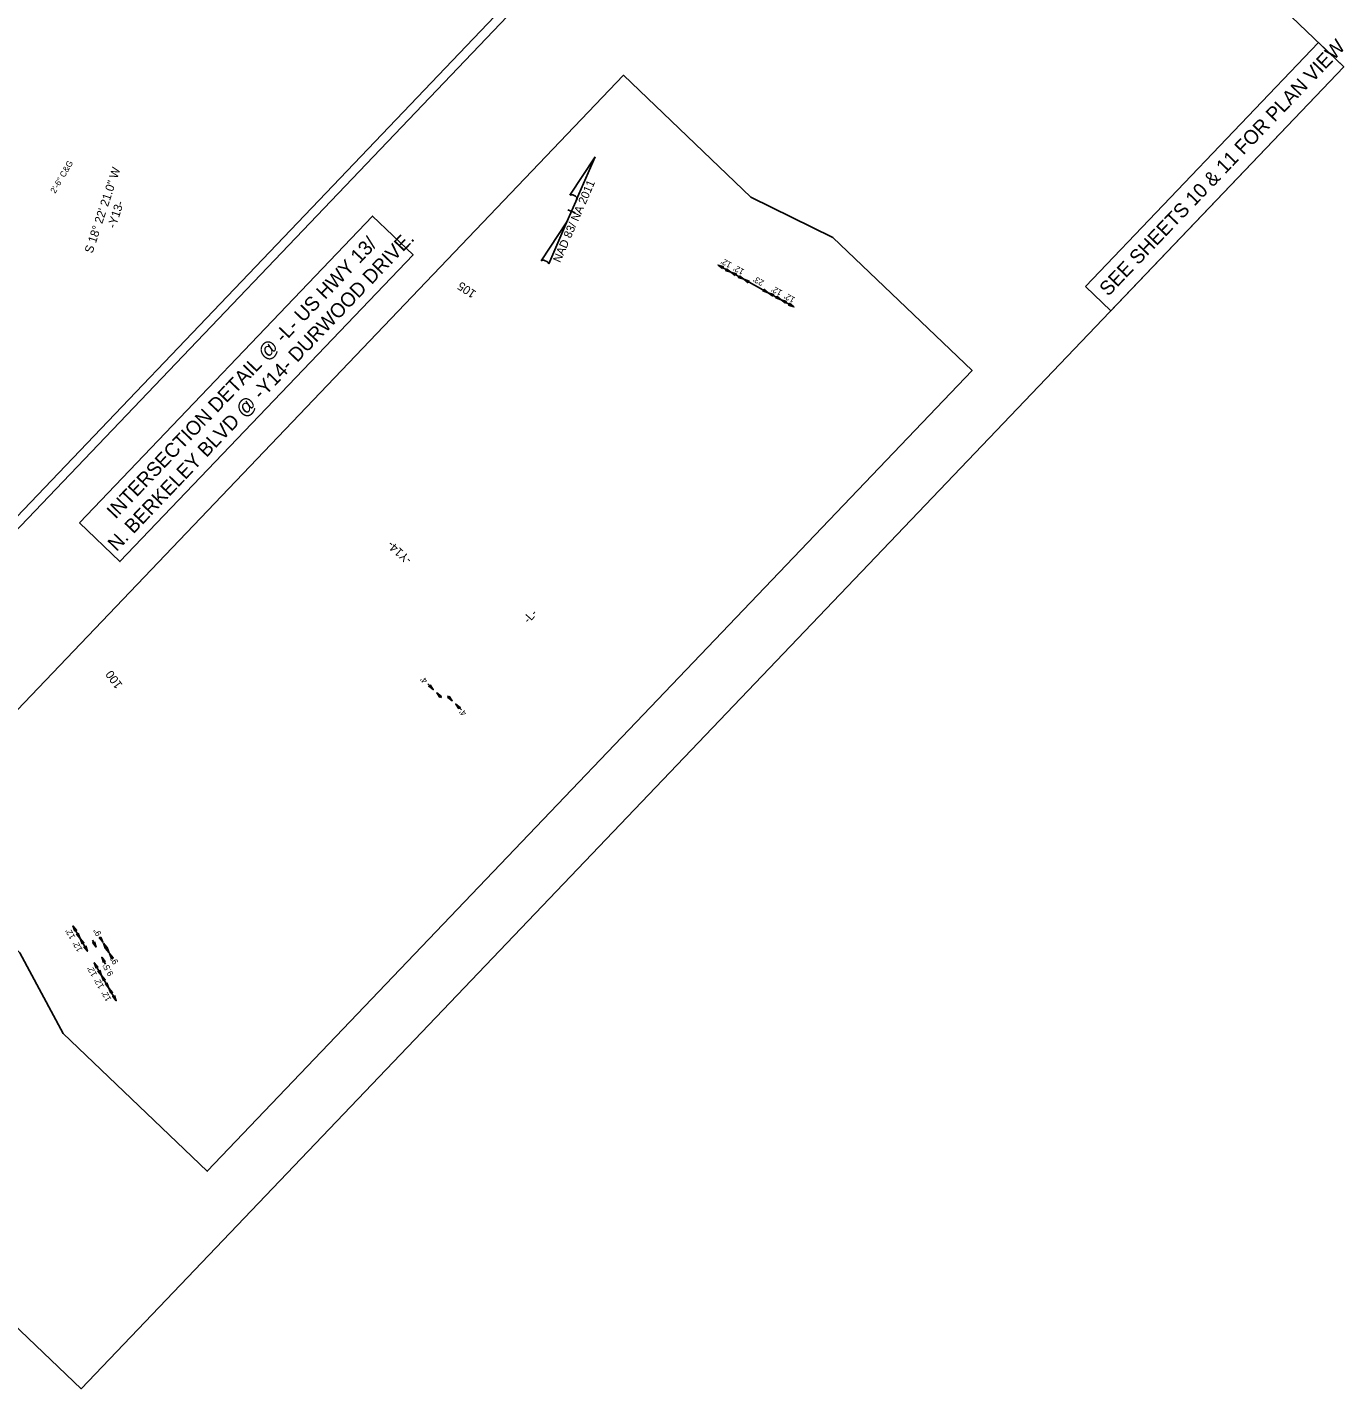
# Model space of a CAD drawing. Extents: x 2326836 to 2328631, y 602012 to 603789.
# Drawn here: x 2327551 to 2328631, y 602012 to 603129 of the extents above; entities that cross this region are included whole.
import ezdxf

# ---------------------------------------------------------------- set-up
doc = ezdxf.new("R2010")
doc.units = 0
for name, color, linetype in [('Default', 7, 'Continuous'), ('Prop Dimension', 7, 'Continuous'), ('Prop Dimension Text', 7, 'Continuous'), ('Prop Horizontal Alignment Direction Label', 7, 'Continuous'), ('Prop Horizontal Alignment Tick Label', 7, 'Continuous'), ('Prop North Arrow NAD83 for Plan Sheets CELL', 7, 'Continuous'), ('Prop Terminator CELL', 7, 'Continuous'), ('Scratch_Level_1', 7, 'Continuous'), ('Sheet Plan CELL', 7, 'Continuous')]:
    doc.layers.add(name, color=color, linetype=linetype)

msp = doc.modelspace()

# ---------------------------------------------------------------- linework, layer by layer
at = {"layer": 'Default'}
for points in [[(2328419.4, 602916.4), (2328610.7, 603116.6), (2328631.4, 603096.8), (2328440.1, 602896.6)], [(2327593.8, 602722.5), (2327834.4, 602974.3), (2327867.6, 602942.6), (2327627, 602690.8)]]:
    msp.add_lwpolyline(points, close=True, dxfattribs=at)
at = {"layer": 'Prop Dimension'}
for p, q in [((2328128.4, 602928.3), (2328117.9, 602934)), ((2328138.9, 602922.5), (2328128.4, 602928.3)), ((2328159.1, 602911.4), (2328138.9, 602922.5)), ((2328169.6, 602905.6), (2328159.1, 602911.4)), ((2328180.1, 602899.8), (2328169.6, 602905.6)), ((2327879.6, 602590.6), (2327884.2, 602585.9)), ((2327887, 602583.1), (2327890.8, 602579.1)), ((2327895.9, 602580.7), (2327899.8, 602576.7)), ((2327902.6, 602573.9), (2327907.3, 602569.2)), ((2327588.4, 602392), (2327594.4, 602381.6)), ((2327594.4, 602381.6), (2327600.4, 602371.2)), ((2327604.4, 602380.3), (2327607.5, 602374.6)), ((2327610.3, 602383), (2327613, 602378.5)), ((2327613.4, 602377.9), (2327616.1, 602373.4)), ((2327612.1, 602366.3), (2327615.2, 602360.5)), ((2327615.4, 602374.5), (2327618.1, 602370)), ((2327618.5, 602369.3), (2327621.2, 602364.8)), ((2327606, 602361.7), (2327612, 602351.3)), ((2327612, 602351.3), (2327618, 602340.9)), ((2327618, 602340.9), (2327624, 602330.6))]:
    msp.add_line(p, q, dxfattribs=at)
at = {"layer": 'Prop North Arrow NAD83 for Plan Sheets CELL'}
for p, q in [((2327996.2, 602991.5), (2328017, 603022.9)), ((2328017, 603022.8), (2328001.8, 602987.8)), ((2328017, 603022.8), (2328017, 603022.9)), ((2328017, 603022.8), (2328017, 603022.9)), ((2327993.9, 602969.6), (2328002.3, 602988.8)), ((2328001.8, 602987.8), (2328002.2, 602988.8)), ((2327993.9, 602969.6), (2327972.7, 602937.5)), ((2327979, 602935), (2327993.9, 602969.6)), ((2327994.7, 602979.3), (2327994.6, 602979.4)), ((2327994.7, 602979.3), (2328000.6, 602976.8)), ((2327997.3, 602978.2), (2327994.7, 602979.3))]:
    msp.add_line(p, q, dxfattribs=at)
for centre, start_param, end_param in [((2327999.1, 602989.8), 0.216388, 2.908219), ((2327975.8, 602936.1), 0.201328, 3.141593)]:
    msp.add_ellipse(centre, major_axis=(3.09, -1.37), ratio=0.461098, start_param=start_param, end_param=end_param, dxfattribs=at)
at = {"layer": 'Prop Terminator CELL'}
for points in [[(2328121.5, 602931.2), (2328117.9, 602934), (2328122.3, 602932.6), (2328121.4, 602932.1)], [(2328124.9, 602931.1), (2328128.4, 602928.3), (2328124.1, 602929.7), (2328125, 602930.2)], [(2328132, 602925.4), (2328128.4, 602928.3), (2328132.8, 602926.8), (2328131.9, 602926.4)], [(2328135.4, 602925.3), (2328138.9, 602922.5), (2328134.6, 602924), (2328135.5, 602924.4)], [(2328142.5, 602919.6), (2328138.9, 602922.5), (2328143.3, 602921), (2328142.4, 602920.6)], [(2328155.5, 602914.3), (2328159.1, 602911.4), (2328154.7, 602912.9), (2328155.6, 602913.3)], [(2328162.7, 602908.6), (2328159.1, 602911.4), (2328163.4, 602909.9), (2328162.6, 602909.5)], [(2328166, 602908.5), (2328169.6, 602905.6), (2328165.3, 602907.1), (2328166.2, 602907.5)], [(2328173.2, 602902.8), (2328169.6, 602905.6), (2328174, 602904.1), (2328173.1, 602903.7)], [(2328176.6, 602902.7), (2328180.1, 602899.8), (2328175.8, 602901.3), (2328176.7, 602901.7)], [(2327881.6, 602589.7), (2327884.2, 602585.9), (2327880.4, 602588.6), (2327881.4, 602588.7)], [(2327889.6, 602579.3), (2327887, 602583.1), (2327890.7, 602580.4), (2327889.7, 602580.2)], [(2327897.2, 602580.5), (2327899.8, 602576.7), (2327896.1, 602579.4), (2327897, 602579.6)], [(2327905.2, 602570.1), (2327902.6, 602573.9), (2327906.3, 602571.2), (2327905.4, 602571.1)], [(2327590, 602387.7), (2327588.4, 602392), (2327591.4, 602388.4), (2327590.4, 602388.5)], [(2327592.8, 602385.9), (2327594.4, 602381.6), (2327591.5, 602385.1), (2327592.4, 602385)], [(2327596, 602377.3), (2327594.4, 602381.6), (2327597.4, 602378.1), (2327596.4, 602378.2)], [(2327606.1, 602378.9), (2327607.5, 602374.6), (2327604.7, 602378.2), (2327605.7, 602378.1)], [(2327611.4, 602382.8), (2327613, 602378.5), (2327610, 602382), (2327611, 602381.9)], [(2327615, 602373.6), (2327613.4, 602377.9), (2327616.4, 602374.4), (2327615.4, 602374.5)], [(2327598.9, 602375.5), (2327600.4, 602371.2), (2327597.5, 602374.7), (2327598.5, 602374.6)], [(2327613.5, 602361.9), (2327612.1, 602366.3), (2327614.9, 602362.7), (2327614, 602362.8)], [(2327616.5, 602374.2), (2327618.1, 602370), (2327615.1, 602373.4), (2327616.1, 602373.3)], [(2327620.1, 602365), (2327618.5, 602369.3), (2327621.5, 602365.8), (2327620.5, 602365.9)], [(2327607.6, 602357.4), (2327606, 602361.7), (2327608.9, 602358.2), (2327608, 602358.3)], [(2327610.4, 602355.6), (2327612, 602351.3), (2327609, 602354.8), (2327610, 602354.7)], [(2327613.6, 602347), (2327612, 602351.3), (2327615, 602347.8), (2327614, 602347.9)], [(2327616.4, 602345.2), (2327618, 602340.9), (2327615.1, 602344.4), (2327616, 602344.4)], [(2327619.6, 602336.7), (2327618, 602340.9), (2327621, 602337.4), (2327620, 602337.5)], [(2327622.5, 602334.8), (2327624, 602330.6), (2327621.1, 602334.1), (2327622.1, 602334)]]:
    msp.add_lwpolyline(points, close=True, dxfattribs=at)
at = {"layer": 'Scratch_Level_1'}
for points in [[(2326885.1, 602788.9), (2327620.5, 603558.6), (2327714.8, 603468.5), (2327770.2, 603526.4), (2328049.9, 603259.1), (2327259.2, 602431.5)], [(2327580.3, 602303.8), (2327544.9, 602370), (2327444.3, 602466.1), (2328040.2, 603089.8), (2328144.8, 602989.9), (2328212, 602956.7), (2328326.3, 602847.5), (2327698.7, 602190.7)]]:
    msp.add_lwpolyline(points, close=True, dxfattribs=at)
at = {"layer": 'Sheet Plan CELL'}
for points in [[(2326836, 602737.6), (2327550.3, 603485.2), (2327577.2, 603459.5), (2327678.5, 603565.6), (2327746, 603501.1), (2327828.4, 603587.3), (2327892.9, 603525.7), (2328031.1, 603670.4), (2328251.8, 603459.5), (2327215.5, 602374.9)], [(2327215.5, 602374.9), (2328251.8, 603459.5), (2328631.4, 603096.8), (2327595.1, 602012.3)]]:
    msp.add_lwpolyline(points, close=True, dxfattribs=at)

# ---------------------------------------------------------------- texts
at = {"layer": 'Default'}
for s, p in [('SEE SHEETS 10 & 11 FOR PLAN VIEW', (2328438.1, 602907.9)), ('INTERSECTION DETAIL @ -L- US HWY 13/', (2327623.4, 602725.2)), ('N. BERKELEY BLVD @ -Y14- DURWOOD DRIVE.', (2327624.3, 602698.6))]:
    msp.add_text(s, height=11.666, rotation=46.3032, dxfattribs=at).set_placement(p)
at = {"layer": 'Prop Dimension Text'}
for s, rotation, p in [('2\'-6" C&G', 59.8013, (2327573.9, 602992.4)), ("12'", 151.2094, (2328129.6, 602935.7)), ("12'", 151.2094, (2328139.9, 602930.1)), ("23'", 151.2094, (2328156.1, 602921)), ("12'", 151.2094, (2328171.1, 602912.9)), ("12'", 151.2094, (2328181.6, 602907.1)), ("4'", 134.34, (2327880, 602593.6)), ("4'", 134.5271, (2327912, 602566.9)), ("12'", 120.1408, (2327590.6, 602382.8)), ('9"', 120.7145, (2327612.2, 602385.4)), ("12'", 120.1408, (2327596.6, 602372.5)), ("12'", 120.1408, (2327608.5, 602352.1)), ("9.5'", 118.472, (2327622, 602352.4)), ('9"', 120.7145, (2327626, 602362.2)), ("12'", 120.1408, (2327614.2, 602342.2)), ("12'", 120.1408, (2327620.2, 602331.8))]:
    msp.add_text(s, height=5, rotation=rotation, dxfattribs=at).set_placement(p)
at = {"layer": 'Prop Horizontal Alignment Direction Label'}
for s, rotation, p in [('S 18%%d 22\' 21.0" W', 71.6275, (2327604.4, 602943.2)), ('-Y13-', 71.6275, (2327623.2, 602963.7)), ('-Y14-', 138.0763, (2327867.1, 602693.1)), ('-L-', 48.3584, (2327962.4, 602639.6))]:
    msp.add_text(s, height=7, rotation=rotation, dxfattribs=at).set_placement(p)
at = {"layer": 'Prop Horizontal Alignment Tick Label'}
for s, rotation, p in [('105', 145.8198, (2327920, 602912.1)), ('100', 126.0627, (2327629.5, 602589.7))]:
    msp.add_text(s, height=7, rotation=rotation, dxfattribs=at).set_placement(p)
at = {"layer": 'Prop North Arrow NAD83 for Plan Sheets CELL'}
msp.add_text('NAD 83/ NA 2011', height=6.8, rotation=66.5425, dxfattribs=at).set_placement((2327988.3, 602935.6))

doc.saveas('drawing.dxf')
